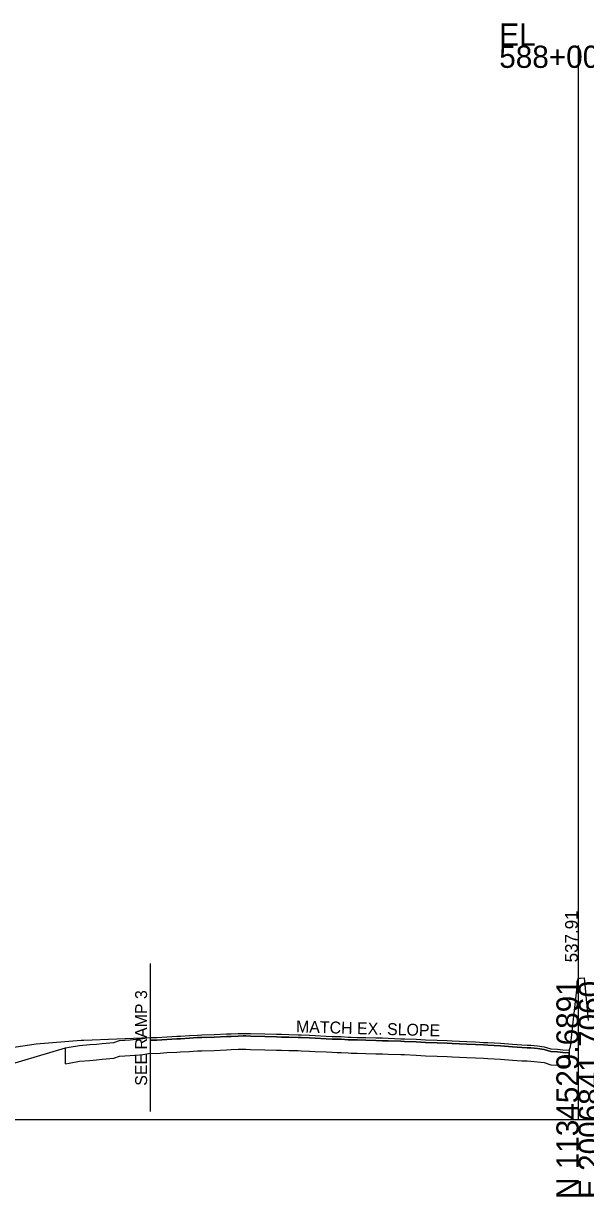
# Model space of a CAD drawing. Extents: x -201 to 2007062, y -213 to 1139737.
# Drawn here: x 1180 to 1250.9, y 2990.3 to 3138.1 of the extents above; entities that cross this region are included whole.
import ezdxf

# ---------------------------------------------------------------- set-up
doc = ezdxf.new("R2010")
doc.units = 0
for name, color, linetype in [('RD_DTM_Design_FG', 7, 'Continuous'), ('RD_GPK_XS_Cell', 7, 'Continuous'), ('RD_XS_ExGround', 7, 'Continuous'), ('RD_XS_ExPaveRet', 7, 'Continuous'), ('RD_XS_PaveOvlay', 7, 'Continuous'), ('RD_XS_SideStreet', 7, 'Continuous'), ('RD_XS_TX_Elev_EX', 7, 'Continuous'), ('RD_XS_TX_Slope', 7, 'Continuous')]:
    doc.layers.add(name, color=color, linetype=linetype)

msp = doc.modelspace()

# ---------------------------------------------------------------- linework, layer by layer
at = {"layer": 'RD_DTM_Design_FG'}
msp.add_lwpolyline([(1126.39, 3036.22), (1145.22, 3017.38), (1159.64, 3002.95), (1165.35, 3004.85), (1177.65, 3008.93), (1178.3, 3009.03), (1181.65, 3009.56), (1187.33, 3010.01), (1187.66, 3010.03), (1191.82, 3010.19), (1196, 3010.35)], dxfattribs=at)
at = {"layer": 'RD_GPK_XS_Cell'}
for p, q in [((1250, 3000), (1250, 3135.35)), ((1000, 3000), (1250, 3000)), ((1250, 3000), (1500, 3000))]:
    msp.add_line(p, q, dxfattribs=at)
at = {"layer": 'RD_XS_ExGround'}
msp.add_lwpolyline([(1176.27, 3006.34), (1185.33, 3009.03), (1185.82, 3009.13), (1187.11, 3009.36), (1188.41, 3009.45), (1189.23, 3009.52), (1189.98, 3009.6), (1191.43, 3009.73), (1192.16, 3009.98), (1193.47, 3010.07), (1194.68, 3010.17), (1195.07, 3010.21), (1195.59, 3010.29), (1196.03, 3010.37), (1196.87, 3010.35), (1198.09, 3010.44), (1199.38, 3010.51), (1199.83, 3010.53), (1200.95, 3010.6), (1201.96, 3010.66), (1202.51, 3010.68), (1204.09, 3010.72), (1205.65, 3010.8), (1206.2, 3010.83), (1207.08, 3010.86), (1207.71, 3010.87), (1208.06, 3010.87), (1208.64, 3010.85), (1210.44, 3010.8), (1211.92, 3010.76), (1212.56, 3010.75), (1213.48, 3010.73), (1214.68, 3010.7), (1215.05, 3010.69), (1216.09, 3010.63), (1216.81, 3010.59), (1218.18, 3010.53), (1218.93, 3010.49), (1219.59, 3010.47), (1220.08, 3010.46), (1220.98, 3010.4), (1221.32, 3010.39), (1222.08, 3010.37), (1223.17, 3010.34), (1224.45, 3010.31), (1225.29, 3010.29), (1226.02, 3010.26), (1227.59, 3010.2), (1228.08, 3010.19), (1229.53, 3010.13), (1230.72, 3010.06), (1232.19, 3010.01), (1233.42, 3009.96), (1234.08, 3009.93), (1235.9, 3009.85), (1236.99, 3009.8), (1238.02, 3009.74), (1238.56, 3009.71), (1240.14, 3009.62), (1241.69, 3009.49), (1242.26, 3009.46), (1242.84, 3009.41), (1243.52, 3009.4), (1243.97, 3009.38), (1244.82, 3009.29), (1245.66, 3009.18), (1246.51, 3008.91), (1247.34, 3008.86), (1248.02, 3008.8), (1248.8, 3008.76), (1248.97, 3009.18), (1249.35, 3012.64), (1249.93, 3017.82), (1250.24, 3017.82), (1250.71, 3017.85), (1251.21, 3012.5)], dxfattribs=at)
at = {"layer": 'RD_XS_ExPaveRet'}
for p, q in [((1196, 3010.03), (1196, 3008.36)), ((1185.33, 3007.03), (1185.33, 3009.03)), ((1199.83, 3008.53), (1200.95, 3008.6)), ((1199.83, 3008.53), (1200.95, 3008.6)), ((1200.95, 3008.6), (1201.96, 3008.66)), ((1200.95, 3008.6), (1201.96, 3008.66)), ((1201.96, 3008.66), (1202.51, 3008.68)), ((1201.96, 3008.66), (1202.51, 3008.68)), ((1202.51, 3008.68), (1204.09, 3008.72)), ((1202.51, 3008.68), (1204.09, 3008.72)), ((1204.09, 3008.72), (1205.65, 3008.8)), ((1204.09, 3008.72), (1205.65, 3008.8)), ((1205.65, 3008.8), (1206.2, 3008.83)), ((1205.65, 3008.8), (1206.2, 3008.83)), ((1206.2, 3008.83), (1207.08, 3008.86)), ((1206.2, 3008.83), (1207.08, 3008.86)), ((1207.08, 3008.86), (1207.71, 3008.87)), ((1207.08, 3008.86), (1207.71, 3008.87)), ((1207.71, 3008.87), (1208.06, 3008.87)), ((1207.71, 3008.87), (1208.06, 3008.87)), ((1208.06, 3008.87), (1208.64, 3008.85)), ((1208.06, 3008.87), (1208.64, 3008.85)), ((1208.64, 3008.85), (1210.44, 3008.8)), ((1208.64, 3008.85), (1210.44, 3008.8)), ((1210.44, 3008.8), (1211.92, 3008.76)), ((1210.44, 3008.8), (1211.92, 3008.76)), ((1211.92, 3008.76), (1212.56, 3008.75)), ((1211.92, 3008.76), (1212.56, 3008.75)), ((1212.56, 3008.75), (1213.48, 3008.73)), ((1212.56, 3008.75), (1213.48, 3008.73)), ((1213.48, 3008.73), (1214.68, 3008.7)), ((1213.48, 3008.73), (1214.68, 3008.7)), ((1214.68, 3008.7), (1215.05, 3008.69)), ((1214.68, 3008.7), (1215.05, 3008.69)), ((1215.05, 3008.69), (1216.09, 3008.63)), ((1215.05, 3008.69), (1216.09, 3008.63)), ((1216.09, 3008.63), (1216.81, 3008.59)), ((1216.09, 3008.63), (1216.81, 3008.59)), ((1216.81, 3008.59), (1218.18, 3008.53)), ((1216.81, 3008.59), (1218.18, 3008.53)), ((1248.81, 3008.76), (1248.81, 3006.76)), ((1185.33, 3007.03), (1185.82, 3007.13)), ((1185.82, 3007.13), (1187.11, 3007.36)), ((1187.11, 3007.36), (1188.41, 3007.45)), ((1188.41, 3007.45), (1189.23, 3007.52)), ((1189.23, 3007.52), (1189.98, 3007.6)), ((1189.98, 3007.6), (1191.43, 3007.73)), ((1191.43, 3007.73), (1192.16, 3007.98)), ((1192.16, 3007.98), (1193.47, 3008.07)), ((1193.47, 3008.07), (1194.68, 3008.17)), ((1194.68, 3008.17), (1195.07, 3008.21)), ((1195.07, 3008.21), (1195.59, 3008.29)), ((1195.59, 3008.29), (1196.03, 3008.37)), ((1196, 3008.36), (1196.03, 3008.37)), ((1196.03, 3008.37), (1196.87, 3008.35)), ((1196.03, 3008.37), (1196.87, 3008.35)), ((1196.87, 3008.35), (1198.09, 3008.44)), ((1196.87, 3008.35), (1198.09, 3008.44)), ((1198.09, 3008.44), (1199.38, 3008.51)), ((1198.09, 3008.44), (1199.38, 3008.51)), ((1199.38, 3008.51), (1199.83, 3008.53)), ((1199.38, 3008.51), (1199.83, 3008.53)), ((1218.18, 3008.53), (1218.93, 3008.49)), ((1218.18, 3008.53), (1218.93, 3008.49)), ((1218.93, 3008.49), (1219.59, 3008.47)), ((1218.93, 3008.49), (1219.59, 3008.47)), ((1219.59, 3008.47), (1220.08, 3008.46)), ((1219.59, 3008.47), (1220.08, 3008.46)), ((1220.08, 3008.46), (1220.98, 3008.4)), ((1220.08, 3008.46), (1220.98, 3008.4)), ((1220.98, 3008.4), (1221.32, 3008.39)), ((1220.98, 3008.4), (1221.32, 3008.39)), ((1221.32, 3008.39), (1222.08, 3008.37)), ((1221.32, 3008.39), (1222.08, 3008.37)), ((1222.08, 3008.37), (1223.17, 3008.34)), ((1222.08, 3008.37), (1223.17, 3008.34)), ((1223.17, 3008.34), (1224.45, 3008.31)), ((1223.17, 3008.34), (1224.45, 3008.31)), ((1224.45, 3008.31), (1225.29, 3008.29)), ((1224.45, 3008.31), (1225.29, 3008.29)), ((1225.29, 3008.29), (1226.02, 3008.26)), ((1225.29, 3008.29), (1226.02, 3008.26)), ((1226.02, 3008.26), (1227.59, 3008.2)), ((1226.02, 3008.26), (1227.59, 3008.2)), ((1227.59, 3008.2), (1228.08, 3008.19)), ((1227.59, 3008.2), (1228.08, 3008.19)), ((1228.08, 3008.19), (1229.53, 3008.13)), ((1228.08, 3008.19), (1229.53, 3008.13)), ((1229.53, 3008.13), (1230.72, 3008.06)), ((1229.53, 3008.13), (1230.72, 3008.06)), ((1230.72, 3008.06), (1232.19, 3008.01)), ((1230.72, 3008.06), (1232.19, 3008.01)), ((1232.19, 3008.01), (1233.42, 3007.96)), ((1232.19, 3008.01), (1233.42, 3007.96)), ((1233.42, 3007.96), (1234.08, 3007.93)), ((1233.42, 3007.96), (1234.08, 3007.93)), ((1234.08, 3007.93), (1235.9, 3007.85)), ((1234.08, 3007.93), (1235.9, 3007.85)), ((1235.9, 3007.85), (1236.99, 3007.8)), ((1235.9, 3007.85), (1236.99, 3007.8)), ((1236.99, 3007.8), (1238.02, 3007.74)), ((1236.99, 3007.8), (1238.02, 3007.74)), ((1238.02, 3007.74), (1238.56, 3007.71)), ((1238.02, 3007.74), (1238.56, 3007.71)), ((1238.56, 3007.71), (1240.14, 3007.62)), ((1238.56, 3007.71), (1240.14, 3007.62)), ((1240.14, 3007.62), (1241.69, 3007.49)), ((1240.14, 3007.62), (1241.69, 3007.49)), ((1241.69, 3007.49), (1242.26, 3007.46)), ((1241.69, 3007.49), (1242.26, 3007.46)), ((1242.26, 3007.46), (1242.84, 3007.41)), ((1242.26, 3007.46), (1242.84, 3007.41)), ((1242.84, 3007.41), (1243.52, 3007.4)), ((1242.84, 3007.41), (1243.52, 3007.4)), ((1243.52, 3007.4), (1243.97, 3007.38)), ((1243.52, 3007.4), (1243.97, 3007.38)), ((1243.97, 3007.38), (1244.82, 3007.29)), ((1243.97, 3007.38), (1244.82, 3007.29)), ((1244.82, 3007.29), (1245.66, 3007.18)), ((1244.82, 3007.29), (1245.66, 3007.18)), ((1245.66, 3007.18), (1246.51, 3006.91)), ((1245.66, 3007.18), (1246.51, 3006.91)), ((1248.81, 3006.76), (1248.81, 3008.43)), ((1185.33, 3007.03), (1185.33, 3007.03)), ((1246.51, 3006.91), (1247.34, 3006.86)), ((1246.51, 3006.91), (1247.34, 3006.86)), ((1247.34, 3006.86), (1248.02, 3006.8)), ((1247.34, 3006.86), (1248.02, 3006.8)), ((1248.02, 3006.8), (1248.8, 3006.76)), ((1248.02, 3006.8), (1248.8, 3006.76)), ((1248.8, 3006.76), (1248.81, 3006.76)), ((1248.8, 3006.76), (1248.81, 3006.76))]:
    msp.add_line(p, q, dxfattribs=at)
for points in [[(1248.8, 3008.43), (1248.02, 3008.47), (1247.34, 3008.53), (1246.51, 3008.58), (1245.66, 3008.85), (1244.82, 3008.96), (1243.97, 3009.05), (1243.52, 3009.06), (1242.84, 3009.08), (1242.26, 3009.12), (1241.69, 3009.16), (1240.14, 3009.29), (1238.56, 3009.37), (1238.02, 3009.41), (1236.99, 3009.47), (1235.9, 3009.52), (1234.08, 3009.6), (1233.42, 3009.63), (1232.19, 3009.68), (1230.72, 3009.73), (1229.53, 3009.8), (1228.08, 3009.85), (1227.59, 3009.87), (1226.02, 3009.93), (1225.29, 3009.95), (1224.45, 3009.98), (1223.17, 3010.01), (1222.08, 3010.04), (1221.32, 3010.06), (1220.98, 3010.07), (1220.08, 3010.12), (1219.59, 3010.14), (1218.93, 3010.16), (1218.18, 3010.19), (1216.81, 3010.25), (1216.09, 3010.29), (1215.05, 3010.35), (1214.68, 3010.37), (1213.48, 3010.4), (1212.56, 3010.41), (1211.92, 3010.43), (1210.44, 3010.46), (1208.64, 3010.51), (1208.06, 3010.54), (1207.71, 3010.54), (1207.08, 3010.52), (1206.2, 3010.49), (1205.65, 3010.47), (1204.09, 3010.39), (1202.51, 3010.34), (1201.96, 3010.33), (1200.95, 3010.27), (1199.83, 3010.2), (1199.38, 3010.17), (1198.09, 3010.11), (1196.87, 3010.02), (1196.03, 3010.03), (1196, 3010.03)], [(1248.81, 3008.43), (1248.8, 3008.43)]]:
    msp.add_lwpolyline(points, dxfattribs=at)
at = {"layer": 'RD_XS_PaveOvlay'}
msp.add_line((1196, 3010.36), (1196, 3010.03), dxfattribs=at)
for points in [[(1196, 3010.36), (1196.03, 3010.37), (1196.87, 3010.35), (1198.09, 3010.44), (1199.38, 3010.51), (1199.83, 3010.53), (1200.95, 3010.6), (1201.96, 3010.66), (1202.51, 3010.68), (1204.09, 3010.72), (1205.65, 3010.8), (1206.2, 3010.83), (1207.08, 3010.86), (1207.71, 3010.87), (1208.06, 3010.87), (1208.64, 3010.85), (1210.44, 3010.8), (1211.92, 3010.76), (1212.56, 3010.75), (1213.48, 3010.73), (1214.68, 3010.7), (1215.05, 3010.69), (1216.09, 3010.63), (1216.81, 3010.59), (1218.18, 3010.53), (1218.93, 3010.49), (1219.59, 3010.47), (1220.08, 3010.46), (1220.98, 3010.4), (1221.32, 3010.39), (1222.08, 3010.37), (1223.17, 3010.34), (1224.45, 3010.31), (1225.29, 3010.29), (1226.02, 3010.26), (1227.59, 3010.2), (1228.08, 3010.19), (1229.53, 3010.13), (1230.72, 3010.06), (1232.19, 3010.01), (1233.42, 3009.96), (1234.08, 3009.93), (1235.9, 3009.85), (1236.99, 3009.8), (1238.02, 3009.74), (1238.56, 3009.71), (1240.14, 3009.62), (1241.69, 3009.49), (1242.26, 3009.46), (1242.84, 3009.41), (1243.52, 3009.4), (1243.97, 3009.38), (1244.82, 3009.29), (1245.66, 3009.18), (1246.51, 3008.91), (1247.34, 3008.86), (1248.02, 3008.8), (1248.8, 3008.76), (1248.81, 3008.76)], [(1196, 3010.03), (1196.03, 3010.03), (1196.87, 3010.02), (1198.09, 3010.11), (1199.38, 3010.17), (1199.83, 3010.2), (1200.95, 3010.27), (1201.96, 3010.33), (1202.51, 3010.34), (1204.09, 3010.39), (1205.65, 3010.47), (1206.2, 3010.49), (1207.08, 3010.52), (1207.71, 3010.54), (1208.06, 3010.54), (1208.64, 3010.51), (1210.44, 3010.46), (1211.92, 3010.43), (1212.56, 3010.41), (1213.48, 3010.4), (1214.68, 3010.37), (1215.05, 3010.35), (1216.09, 3010.29), (1216.81, 3010.25), (1218.18, 3010.19), (1218.93, 3010.16), (1219.59, 3010.14), (1220.08, 3010.12), (1220.98, 3010.07), (1221.32, 3010.06), (1222.08, 3010.04), (1223.17, 3010.01), (1224.45, 3009.98), (1225.29, 3009.95), (1226.02, 3009.93), (1227.59, 3009.87), (1228.08, 3009.85), (1229.53, 3009.8), (1230.72, 3009.73), (1232.19, 3009.68), (1233.42, 3009.63), (1234.08, 3009.6), (1235.9, 3009.52), (1236.99, 3009.47), (1238.02, 3009.41), (1238.56, 3009.37), (1240.14, 3009.29), (1241.69, 3009.16), (1242.26, 3009.12), (1242.84, 3009.08), (1243.52, 3009.06), (1243.97, 3009.05), (1244.82, 3008.96), (1245.66, 3008.85), (1246.51, 3008.58), (1247.34, 3008.53), (1248.02, 3008.47), (1248.8, 3008.43), (1248.81, 3008.43)]]:
    msp.add_lwpolyline(points, dxfattribs=at)
at = {"layer": 'RD_XS_SideStreet'}
msp.add_line((1196, 3019.68), (1196, 3001.01), dxfattribs=at)

# ---------------------------------------------------------------- texts
at = {"layer": 'RD_GPK_XS_Cell'}
for s, p in [('EL', (1240, 3135.35)), ('588+00.00 / 1', (1240, 3132.55))]:
    msp.add_text(s, height=2.8, dxfattribs=at).set_placement(p)
for s, p in [('N 1134529.6891', (1250, 2990)), ('E 2006841.7060', (1252.8, 2990))]:
    msp.add_text(s, height=2.8, rotation=90, dxfattribs=at).set_placement(p)
at = {"layer": 'RD_XS_SideStreet'}
msp.add_text('SEE RAMP 3', height=1.5, rotation=90, dxfattribs=at).set_placement((1195.62, 3004.27))
at = {"layer": 'RD_XS_TX_Elev_EX'}
msp.add_text('537.91', height=1.6, rotation=90, dxfattribs=at).set_placement((1249.9, 3019.82))
at = {"layer": 'RD_XS_TX_Slope'}
msp.add_text('MATCH EX. SLOPE', height=1.5, rotation=358.3671, dxfattribs=at).set_placement((1214.37, 3011))

doc.saveas('drawing.dxf')
